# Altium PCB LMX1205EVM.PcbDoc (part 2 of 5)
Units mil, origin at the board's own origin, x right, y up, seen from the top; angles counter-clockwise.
Board outline 5000 x 5000 mil, 6 copper layers (Top Layer, RF GND, Signal Layer 3, Signal Layer 4, Signal Layer 5, Bottom Layer), stack 61.6 mil thick; 176 components, 99 nets, 572 pads, 2473 vias.
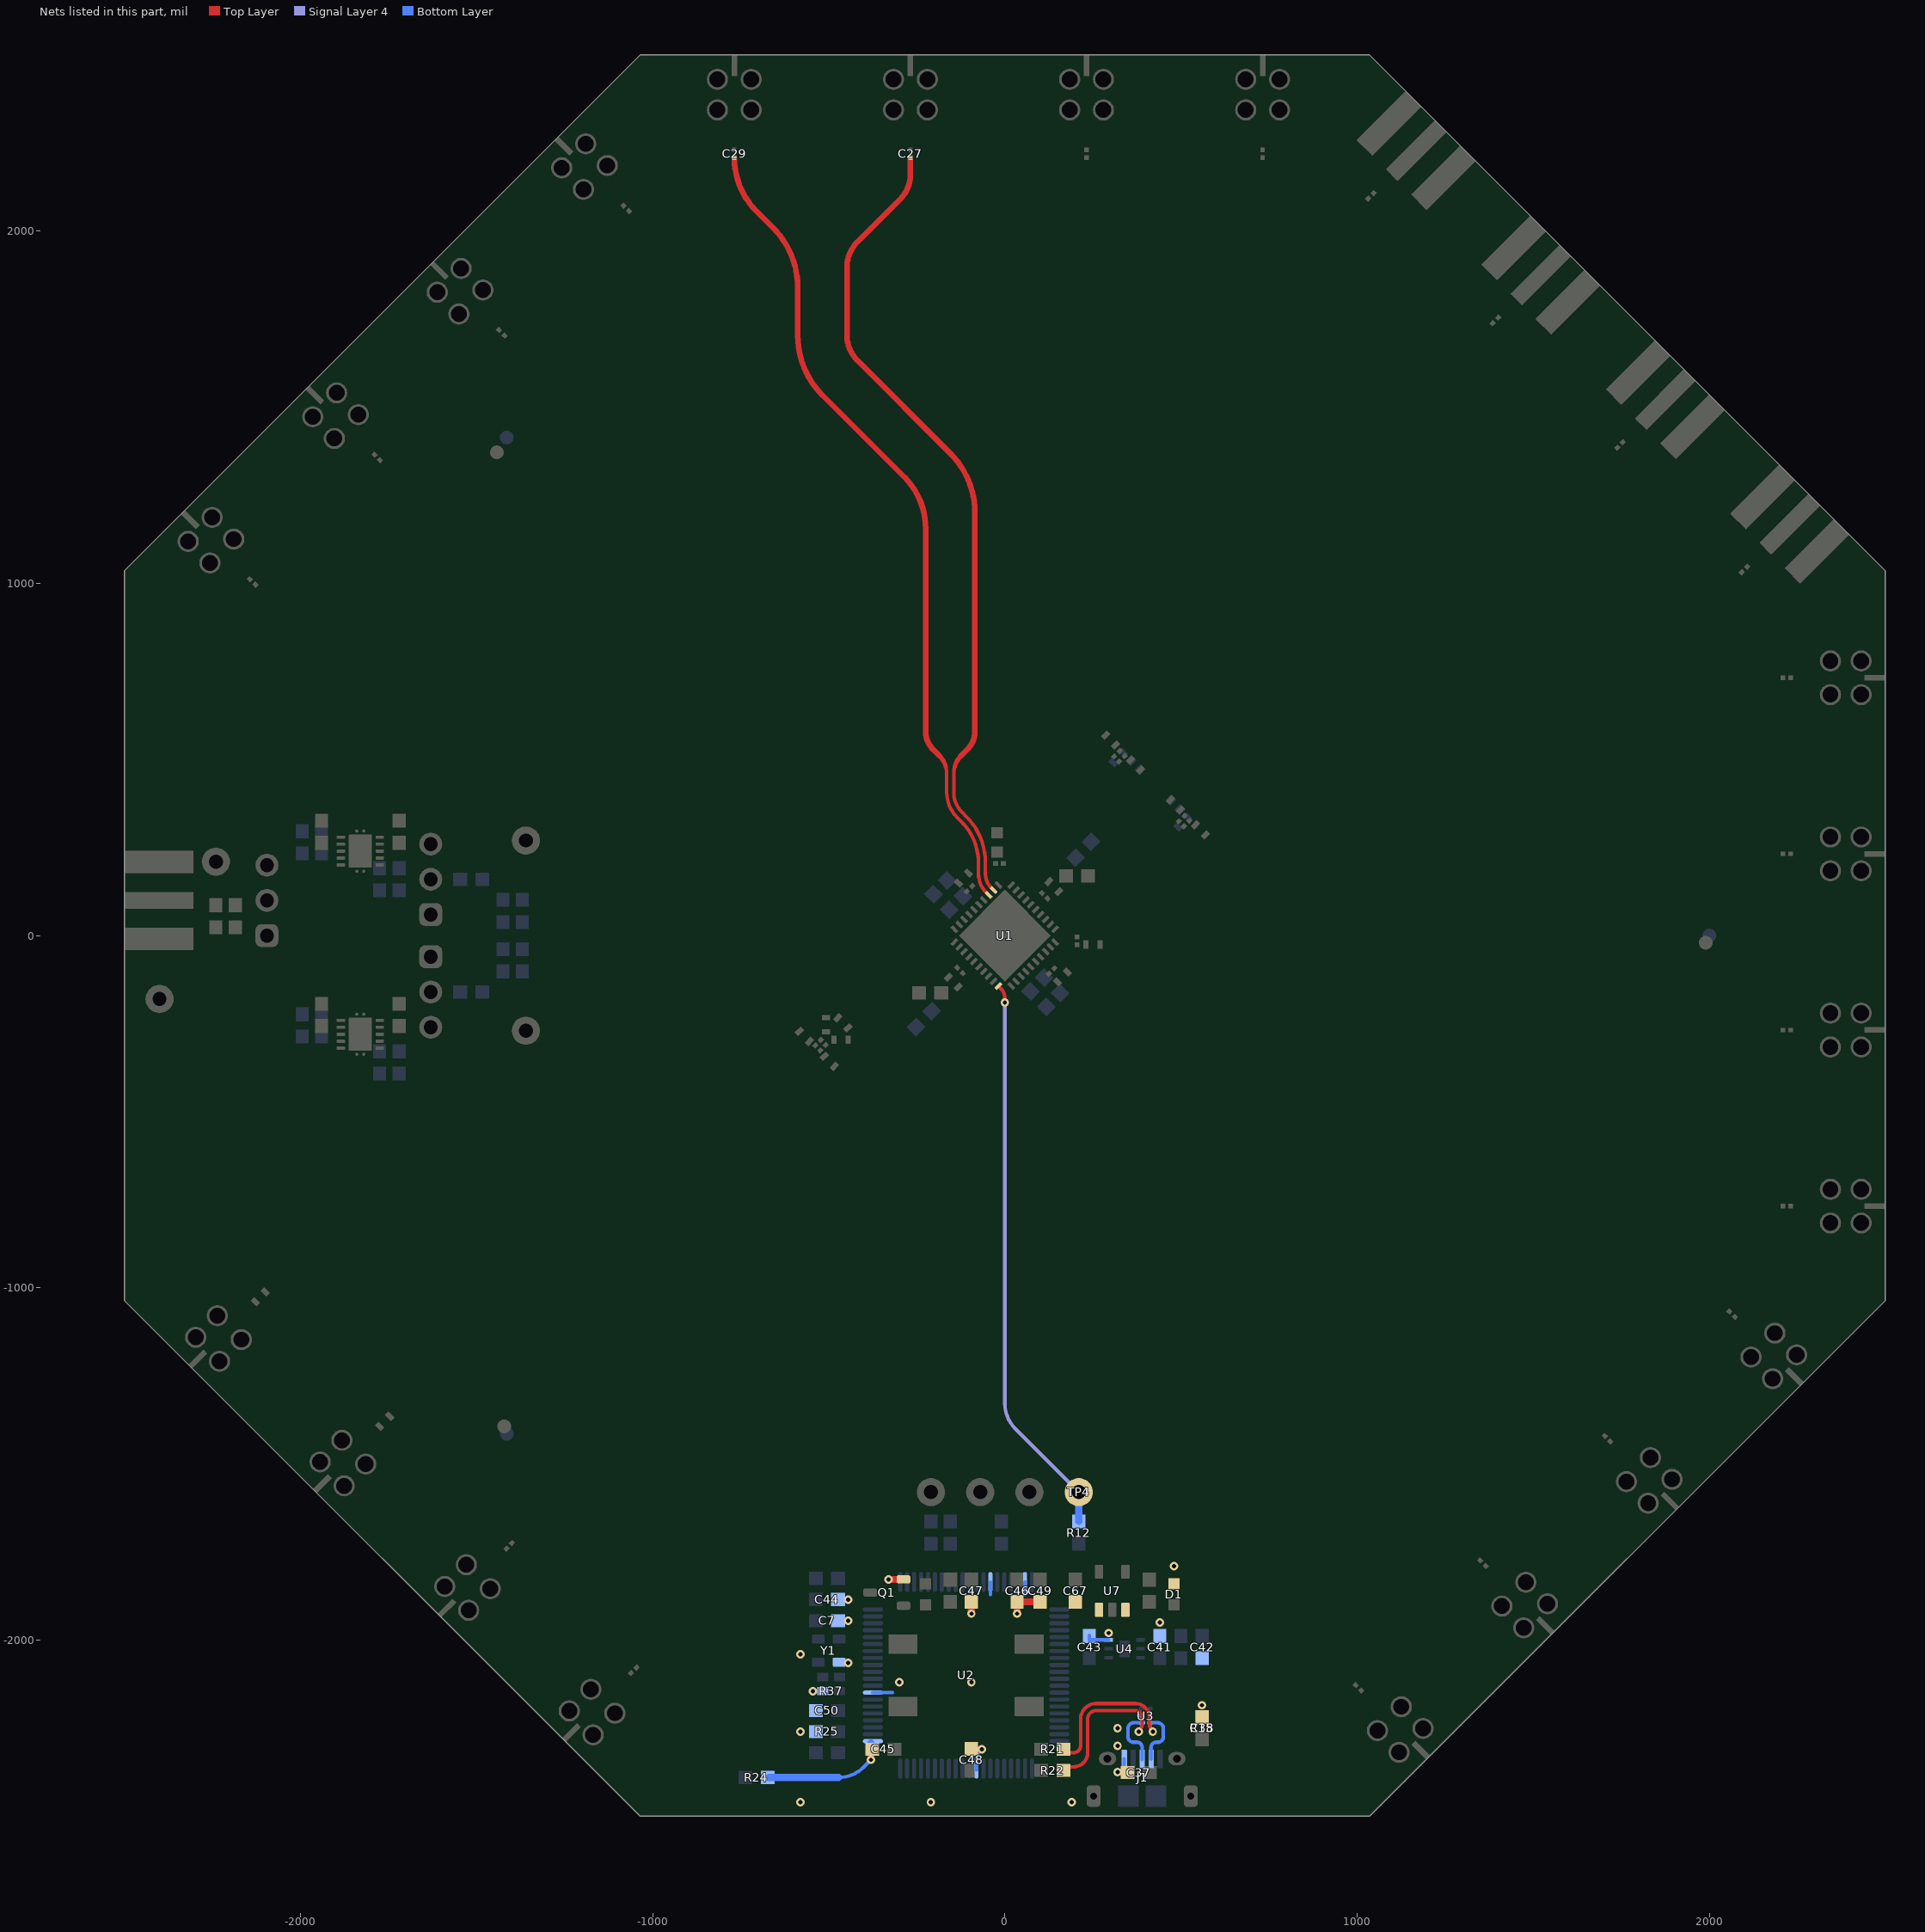
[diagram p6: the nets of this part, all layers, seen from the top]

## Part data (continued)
Y1: library part CMP-0097145-1, "High-Performance BAW Oscillator", Alternate Manufacturer="Texas Instruments", Alternate PartNumber=LMK6CE02400CDLF, Frequency Stability=25ppm, Max Supply Voltage=3.63V, Min Supply Voltage=1.62V, Operating Temperature Range=to, PartNumber=CDC6CE024000ADLFT

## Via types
v1: diameter 24, hole 12, Top Layer to Bottom Layer, tented both sides, 2320 vias
v2: diameter 28, hole 16, Top Layer to Bottom Layer, 120 vias
v3: diameter 19.68, hole 7.87, Top Layer to Bottom Layer, tented both sides, 29 vias
v4: diameter 24, hole 12, Top Layer to Bottom Layer, tented bottom, 3 vias
v5: diameter 236.22, hole 157.48, Top Layer to Bottom Layer, tented both sides, 1 vias

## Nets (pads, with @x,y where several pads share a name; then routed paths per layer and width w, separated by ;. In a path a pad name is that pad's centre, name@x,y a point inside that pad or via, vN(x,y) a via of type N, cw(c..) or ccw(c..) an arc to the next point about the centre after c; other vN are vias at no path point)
C2N: C27.2 U1.32 | length 2332
  Top Layer w10: -142.53,478.75 ccw(c-72.57,460) -145,460 -145,406.72 ccw(c-65,406.72) -121.57,350.15 -109.07,337.65 cw(c-239.31,207.4) -55.12,207.4 -55.12,174.46 ccw(c-2.23,174.46) -39.63,137.06 U1.32@-32.01,129.45
  Top Layer w12: -142.53,478.75 cw(c-72.57,460) -135.3,496.21
  Top Layer w14: -135.3,496.21 cw(c-72.57,460) -123.79,511.21
  Top Layer w16: C27.2@-268,2208 -268,2161.42 cw(c-368,2161.42) -297.29,2090.71 -418.71,1969.29 ccw(c-348,1898.58) -448,1898.58 -448,1880 -448,1703.83 ccw(c-348,1703.83) -418.71,1633.12 -155.29,1369.71 cw(c-325,1200) -85,1200 -85,580 cw(c-157.43,580) -106.21,528.79 -123.79,511.21
C2P: C29.2 U1.33 | length 2332
  Top Layer w10: -167.47,478.75 cw(c-237.43,460) -165,460 -165,406.72 ccw(c-65,406.72) -135.71,336 -123.66,323.96 cw(c-241.62,206) -74.8,206 -74.8,174.4 ccw(c-2.38,174.4) -53.59,123.19 U1.33@-45.93,115.53
  Top Layer w12: -174.7,496.21 cw(c-237.43,460) -167.47,478.75
  Top Layer w14: -186.21,511.21 cw(c-237.43,460) -174.7,496.21
  Top Layer w16: C29.2@-768,2208 ccw(c-554.13,2208) -705.36,2056.77 -658.29,2009.71 cw(c-828,1840) -588,1840 -588,1703.83 ccw(c-348,1703.83) -517.71,1534.13 -285.4,1301.82 cw(c-431.23,1156) -225,1156 -225,580 ccw(c-152.57,580) -203.79,528.79 -186.21,511.21
CSB: R12.2 TP4.1 U1.10 | length 1607.3
  Top Layer w10: U1.10@-17.09,-144.37 -10.83,-150.64 cw(c-36.97,-176.78) 0,-176.78 v1(0,-190)
  Signal Layer 4 w10: v1(0,-190) 0,-1328.58 ccw(c100,-1328.58) 29.29,-1399.29 TP4.1@210,-1580
  Bottom Layer w20: R12.2@210,-1663.5 TP4.1@210,-1580
D+: J1.3 R22.1 U3.1 | length 618.4
  Top Layer w10: R22.1@156.5,-2360 195,-2360 ccw(c195,-2320) 235,-2320 235,-2225 cw(c260,-2225) 260,-2200 370,-2200 cw(c370,-2220) 390,-2220 390,-2235.86 cw(c355.86,-2235.86) v1(380,-2260) ; R22.1@160,-2370 R22.1@166.5,-2370
  Bottom Layer w10: v1(380,-2260) ccw(c357.85,-2237.85) 389.17,-2237.85 U3.1@389.17,-2234.68 365.31,-2234.68 ccw(c365.32,-2250) 350,-2250 350,-2275 ccw(c365,-2275) 365,-2290 375,-2290 cw(c375,-2305) 390,-2305 J1.3@390,-2337.6 J1.3@390,-2339.39
D-: J1.2 R21.1 U3.6 | length 613
  Top Layer w10: R21.1@160,-2310 R21.1@166.5,-2310 ; R21.1@165,-2320 195,-2320 ccw(c195,-2300) 215,-2300 215,-2225 cw(c260,-2225) 260,-2180 370,-2180 cw(c370,-2220) 410,-2220 410,-2235.86 ccw(c444.14,-2235.86) v1(420,-2260)
  Bottom Layer w10: J1.2@415,-2337.6 415,-2305 cw(c430,-2305) 430,-2290 435,-2290 ccw(c435,-2275) 450,-2275 450,-2250.57 ccw(c434.12,-2250.57) 434.12,-2234.68 U3.6@411.81,-2234.69 411.81,-2240.23 ccw(c439.77,-2240.23) v1(420,-2260)
DGND: C7.2 C37.2 C38.2 C41.2 C42.2 C43.2 C44.2 C45.2 C46.2 C47.2 C48.2 C49.2 C50.2 C67.2 D1.2 J1.5 Q1.2 R15.1 R24.1 R25.1 R37.1 U2.14 U2.19 U2.49 U2.61 U2.68 U3.2 U4.3 U7.1 U7.3 Y1.2 | length 891.8
  Top Layer w20: v1(-380,-2340) C45.2@-380,-2310 ; v1@-325,-1828 -287.76,-1828 -283.16,-1828 Q1.2@-282.76,-1827.6 ; C48.2@-95,-2307.01 -92.01,-2310 v1(-65,-2310) ; v1(-95,-1925) C47.2@-95,-1892.99 ; v1(35,-1925) C46.2@35,-1892.99 ; C46.2@35,-1891.5 C49.2@100,-1891.5 ; R15.1@560,-2227.01 R15.1@560,-2217.01
  Bottom Layer w9: 378.19,-2215 U3.2@388.19,-2215
  Bottom Layer w10: -471.42,-2390 ccw(c-471.42,-2290) -400.71,-2360.71 v1(-380,-2340) ; U2.68@-374.76,-2149.21 -319.21,-2149.21 ; v1(-330,-1828) v1@-325,-1828 ; U2.49@-80.47,-2368.27 U2.49@-80.47,-2364.76 -80.47,-2333.21 cw(c-61.79,-2333.21) -75,-2320 v1(-65,-2310) ; -41.1,-1871.1 U2.14@-41.1,-1835.24 ; 57.32,-1870.24 U2.19@57.32,-1835.24 ; C43.2@240,-1987.01 240,-1999.41 U4.3@294.72,-1999.41 ; J1.5@338.82,-2358.71 J1.5@338.82,-2337.6 J1.5@339,-2337.78
  Bottom Layer w20: R24.1@-670,-2390 -471.42,-2390 ; v1(-380,-2340) U2.61@-380,-2291.1
  other v1: -580,-2460 -210,-2460 190,-2460 320,-2375 320,-2300 -580,-2260 320,-2250 560,-2185 -545,-2145 -300,-2120 -95,-2120 -445,-2065 -580,-2040 295,-1980 440,-1950 -445,-1945 -445,-1885 480,-1790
